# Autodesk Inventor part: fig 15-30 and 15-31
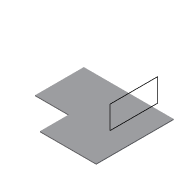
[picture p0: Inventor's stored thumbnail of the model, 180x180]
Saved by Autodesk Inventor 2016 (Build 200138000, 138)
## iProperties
Created: 2005-03
Part Number: fig 15-30 and 15-31
Document SubType Name: Sheet Metal
Designer: CADCIM
Manufacturer: Standard
Standards Organization: Custom
Density: 1 g/cm^3
Sheet Metal Rule: Default
Material: Generic
Appearance: Default
Author: CADCIM
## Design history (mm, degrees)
node "Face1"
  sketch "Sketch1"
    geometry: L1 (29.25, 32.25)-(-19.875, 32.25); L2 (-19.875, 32.25)-(-19.875, 5.625); L3 (-19.875, 5.625)-(-1.5, 5.625); L4 (-1.5, 5.625)-(-1.5, -10.125); L5 (-1.5, -10.125)-(29.25, -10.125); L6 (29.25, -10.125)-(29.25, 32.25)
    constraints: 12 end point, 4 parallel, 1 horizontal, 1 perpendicular
sketch "Sketch2"
  geometry: L1 (-12.475, 7.526)-(-25.013, 7.526); L2 (-25.013, 7.526)-(-25.013, 33.56); L3 (-25.013, 33.56)-(-12.475, 33.56); L4 (-12.475, 33.56)-(-12.475, 7.526)
  constraints: 8 end point, 2 parallel, 1 horizontal, 1 perpendicular
body "Solid1"
face "Plate1" dims "Thickness" = 0.5
other parameters: "BendRadius" = 0.5 (= Thickness), "BendReliefWidth" = 0.5 (= Thickness), "BendReliefDepth" = 0.25 (= 0.5 x Thickness), "CornerReliefSize" = 2 (= 4 x Thickness), "SeamGap" = 0.01, "MinimumRemnant" = 1 (= 2 x Thickness), "TransitionRadius" = 0.5 (= BendRadius), "d0" = 0.5 (= BendRadius), "JacobiRadiusSize" = 0.5 (= Thickness), "GapSize" = 0.5 (= Thickness)
